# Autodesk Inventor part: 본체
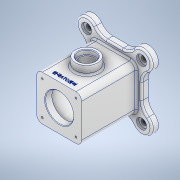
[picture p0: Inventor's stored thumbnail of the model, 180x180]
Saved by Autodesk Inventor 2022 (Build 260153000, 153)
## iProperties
Created: 2022-05
Part Number: 본체
Material: 알루미늄 6061
Document SubType Name: Modeling
Designer: Admin
Density: 2.7 g/cm^3
Appearance: 알루미늄 - 평지
Mass: 1070.84 g
Surface Area: 876.223 cm^2
Volume: 396.606 cm^3
Author: Admin
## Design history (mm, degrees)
sketch "스케치1"
  geometry: L1 (-68.6, 0)-(68.6, 0) reference; L2 (0, -68.6)-(0, 68.6) reference; L3 (-49, 49)-(49, 49); L4 (49, 49)-(49, -49); L5 (49, -49)-(-49, -49); L6 (-49, -49)-(-49, 49); L7 (-49, 49)-(49, -49); L8 (49, 49)-(-49, -49); 1 further point
  constraints: 12 end point, 2 midpoint, 2 parallel, 1 horizontal, 1 perpendicular
  dimensions: "d0" = 98 distance of L3.start L3.end; "d1" = 98 distance of L3.end L4.end
extrude "돌출1" new body sketch "스케치1" distance "d2" = 12; taper "d3" = 0 deg
sketch "스케치2"
  geometry: L1 (-40, 40)-(40, 40); L2 (40, 40)-(40, -40); L3 (40, -40)-(-40, -40); L4 (-40, -40)-(-40, 40); L5 (-40, 40)-(40, -40); L6 (40, 40)-(-40, -40); 1 further point
  constraints: 12 end point, 2 midpoint, 2 parallel, 1 horizontal, 1 perpendicular
  dimensions: "d4" = 80 distance of L1.start L1.end; "d5" = 80 distance of L1.end L2.end
extrude "돌출2" join sketch "스케치2" distance "d6" = 98; taper "d7" = 0 deg
node "작업 평면1"
sketch "스케치4"
  geometry: L1 (0, -22)-(0, 132) reference; L2 (-49, 12)-(49, 12) reference; C1 r 20 at (0, 61); 1 further point
  constraints: 1 centre point, 1 point on line
  dimensions: "d10" = 40 diameter of C1; "d11" = 49 distance from line of L2 C1.centre
extrude "돌출3" join sketch "스케치4" stored distance "d12" = 98; taper "d13" = 0 deg
sketch "스케치5"
  geometry: L1 (0, 83)-(0, -71) reference; L2 (49, 49)-(-49, 49) reference; 2 further points
  constraints: 1 point on line
  dimensions: "d14" = 49 distance from line of L2 point (0, 0)
hole "구멍1" sketch "스케치5" at (0, 0) diameter "d15" = 25; stored, may be unused: countersink angle "d19" = 90 deg, drill point angle "d21" = 0 deg; dims "d16" = 18, "d17" = 30, "d18" = 8, "d20" = 30
sketch "스케치6"
  geometry: L1 (0, -22)-(0, 132) reference; L2 (0, 110)-(25, 110); L3 (25, 110)-(25, 98); L4 (25, 98)-(0, 98); L5 (0, 98)-(0, 110); L6 (0, 98)-(35, 98); L7 (35, 98)-(35, 12); L8 (35, 12)-(0, 12); L9 (0, 12)-(0, 98); L10 (49, 0)-(-49, 0) reference; L11 (0, 12)-(25, 12); L12 (25, 12)-(25, 0); L13 (25, 0)-(0, 0); L14 (0, 0)-(0, 12); 4 further points
  constraints: 24 end point, 6 parallel, 3 horizontal, 3 perpendicular, 3 point on line
  dimensions: "d22" = 50 diameter of L12 L1; "d23" = 70 diameter of L7 L1; "d24" = 12 distance between parallel lines of L2 L4; "d25" = 12 distance between parallel lines of L10 L8; "d26" = 86 distance of L8.end L4.end
revolve "회전1" sketch "스케치6" stored, may be unused: angle "d27" = 90 deg
sketch "스케치7"
  geometry: L1 (0, -69.8)-(0, 75.8) reference; L2 (-68.6, 0)-(68.6, 0) reference; L3 (-30, 30)-(30, 30); L4 (30, 30)-(30, -30); L5 (30, -30)-(-30, -30); L6 (-30, -30)-(-30, 30); L7 (-30, 30)-(30, -30); L8 (30, 30)-(-30, -30); 6 further points
  constraints: 12 end point, 5 coincident, 2 midpoint, 2 parallel, 1 horizontal, 1 perpendicular
  dimensions: "d29" = 60 distance of L3.start L3.end; "d30" = 60 distance of L3.end L4.end
hole "구멍2" sketch "스케치7" at (30, 30), (-30, 30), (-30, -30), (30, -30) diameter "d31" = 3.242; stored, may be unused: countersink angle "d35" = 90 deg, drill point angle "d37" = 118 deg; dims "d32" = 8, "d33" = 30, "d34" = 8, "d36" = 10
sketch "스케치8"
  geometry: L1 (68.6, 0)-(-68.6, 0) reference; L2 (0, -69.8)-(0, 75.8) reference; L3 (0, 0)-(78.013, 78.013); L4 (-49, 49)-(49, 49) reference; C1 r 70 at (0, 0); C2 r 18 at (49, 49); 1 further point
  constraints: 2 centre point, 2 end point, 1 coincident
  dimensions: "d38" = 140 diameter of C1; "d39" = 45 deg angle of L1 L3; "d40" = 36 diameter of C2
extrude "돌출4" join sketch "스케치8" distance "d41" = 12; taper "d42" = 0 deg
fillet "모깎기1" dims "d43" = 25
fillet "모깎기2" dims "d47" = 25
sketch "스케치9"
  geometry: L1 (0, -93.8)-(0, 93.8) reference; L2 (93.8, 0)-(-93.8, 0) reference; L3 (30, 30)-(-30, 30); L4 (-30, 30)-(-30, -30); L5 (-30, -30)-(30, -30); L6 (30, -30)-(30, 30); L7 (30, 30)-(-30, -30); L8 (-30, 30)-(30, -30); C1 r 1.621 at (30, 30) reference; C2 r 1.621 at (30, -30) reference; C3 r 1.621 at (-30, -30) reference; C4 r 1.621 at (-30, 30) reference; 5 further points
  constraints: 12 end point, 4 coincident, 2 midpoint, 2 parallel, 1 horizontal, 1 perpendicular
  dimensions: "d48" = 60 distance of L5.end L3.start; "d49" = 60 distance of L4.end L5.end
hole "구멍3" sketch "스케치9" at (30, 30), (30, -30), (-30, -30), (-30, 30) diameter "d50" = 3.242; stored, may be unused: countersink angle "d54" = 90 deg, drill point angle "d56" = 118 deg; dims "d51" = 8, "d52" = 4, "d53" = 2, "d55" = 10
fillet "모깎기3" dims "d57" = 10
chamfer "모따기1" distance "d58" = 1; stored, may be unused: second distance "d59" = 2, angle "d60" = 45 deg
sketch "스케치10"
  geometry: A1 r 18 centre (49, 49) between (59.465, 34.355) and (34.355, 59.465) reference; A2 r 18 centre (-49, 49) between (-34.355, 59.465) and (-59.465, 34.355) reference; A3 r 18 centre (-49, -49) between (-59.465, -34.355) and (-34.355, -59.465) reference; A4 r 18 centre (49, -49) between (34.355, -59.465) and (59.465, -34.355) reference; 5 further points
  constraints: 4 coincident
hole "구멍4" sketch "스케치10" at (49, 49), (-49, 49), (-49, -49), (49, -49) diameter "d61" = 10; stored, may be unused: countersink angle "d65" = 90 deg, drill point angle "d67" = 0 deg; dims "d62" = 8, "d63" = 18, "d64" = 4, "d66" = 12
sketch "스케치11"
  geometry: L1 (30, 34)-(30, -120) reference; L2 (60, -98)-(0, -98) reference; 2 further points
  constraints: 1 point on line, 1 other
  dimensions: "d68" = 10 distance from line of L2 point (30, -88)
feature "엠보싱1" sketch "스케치11" dims "d0" = 98, "d1" = 98, "d69" = 0.5, "d70" = 0
fillet "모깎기4" dims "d71" = 3
node "솔리드1"
pattern_circular "원형 패턴1" dims angle "d45" = 360 deg
feature "A9D066F2-1C7D-4E18-AEED-F7BC21143FA4" dims "d15" = 25, "d16" = 18, "d17" = 30, "d18" = 8, "d19" = 90 deg, "d20" = 30, "d21" = 0
other parameters: "d9" = 55
